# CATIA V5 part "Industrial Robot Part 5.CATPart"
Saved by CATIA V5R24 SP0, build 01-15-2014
Part number: Industrial Robot Part 5
Source: Unknown
Material "Grey": density 7860 kg/m3, Young's modulus 2e+11 Pa, Poisson ratio 0.266
Bounding box of the stored display mesh (mm): x -358.459 to 335.848, y -201.422 to 286.124, z -826.785 to 638.652
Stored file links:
  C:\Users\cdl\Downloads\2024_CAD_final\p2\Industrial Robot Part 5.CATPart
  D:\Program Files\Dassault Systemes\B24\win_b64\startup\materials\Catalog.CATMaterial
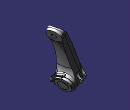
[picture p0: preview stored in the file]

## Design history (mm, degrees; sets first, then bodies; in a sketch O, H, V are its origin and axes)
Body1 (main body), material "Grey"
  Solid1 "Solid 1": solid without history
  Translate1: Direction (1, 0, 0), Length -419, ToTransfor Solid1
  Translate2: Direction (0, 0, 1), Length -1284, ToTransfor Translate1
  Translate3: Direction (0, 1, 0), Length 268, ToTransfor Translate2
  Rotate1: Axis X axis, Angle 337, ToTransfor Translate3
  Rotate2: Axis Z axis, Angle 284, ToTransfor Rotate1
